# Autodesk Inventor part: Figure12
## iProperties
Shininess: 77.0
Length Units: 11269
Angle Units: 11279
Time Units: 11290
Mass Units: 11283
Length Display Precision: 3
Angle Display Precision: 2
Created: 2002-01
Part Number: Figure12
Document SubType Name: Modeling
Designer: ***
Density: 0.0
Volumn: 0.0
Area: 0.0
PropertySet Name: Model Information
Control State: 0
Master: False
Checked Out: False
Author: ***
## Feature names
1. Sweep1
2. Split4
